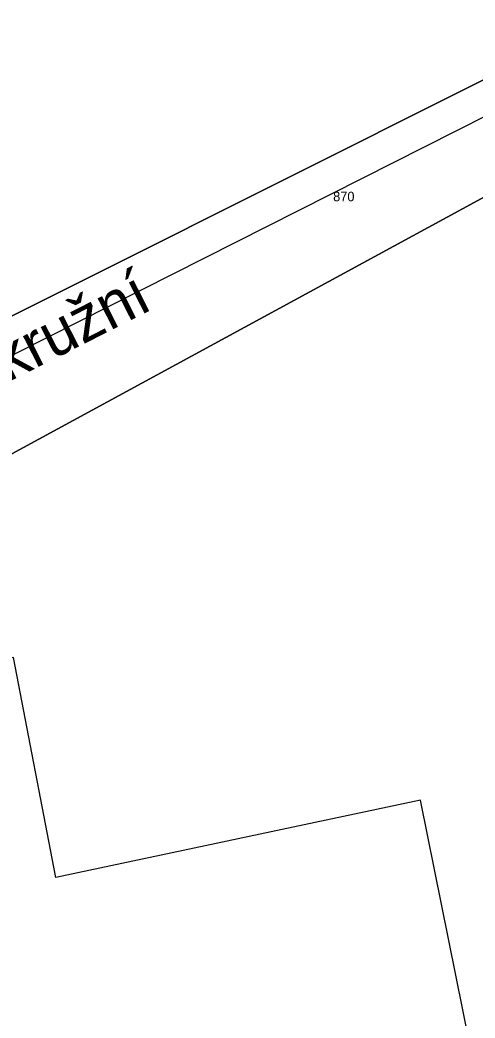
# Model space of a CAD drawing. Extents: x -873642 to -872917, y -1012962 to -1012567.
# Drawn here: x -873481.3 to -873440.9, y -1012917 to -1012828.2 of the extents above; entities that cross this region are included whole.
import ezdxf

# ---------------------------------------------------------------- set-up
doc = ezdxf.new("R2010")
doc.units = 0
for name, color, linetype in [('cisla_parcelni_kn', 7, 'Continuous'), ('osy_ulic', 7, 'Continuous'), ('parcely_kn', 7, 'Continuous'), ('ulice', 7, 'Continuous')]:
    doc.layers.add(name, color=color, linetype=linetype)

msp = doc.modelspace()

# ---------------------------------------------------------------- linework, layer by layer
at = {"layer": 'osy_ulic'}
msp.add_lwpolyline([(-873411.85, -1012822.53), (-873495.73, -1012864.97), (-873510.64, -1012868.38), (-873524.3, -1012868.21), (-873541.44, -1012862.33)], dxfattribs=at)
at = {"layer": 'parcely_kn'}
for points in [[(-873491.56, -1012871.97), (-873407.44, -1012826.19), (-873370.67, -1012811.62), (-873352.28, -1012804.24), (-873327.22, -1012794.59), (-873317.65, -1012791.79), (-873296.21, -1012784.7), (-873295.08, -1012789.07), (-873304.48, -1012791.83), (-873302.28, -1012798.85), (-873296.89, -1012797.13), (-873293, -1012795.88), (-873288.89, -1012809.97), (-873206.66, -1012788.54), (-873209.55, -1012779.29), (-873212.49, -1012767.05), (-873213.62, -1012762.14), (-873185.58, -1012756.25), (-873148.18, -1012749.22)], [(-873491.56, -1012871.97), (-873407.44, -1012826.19), (-873370.67, -1012811.62), (-873352.28, -1012804.24), (-873327.22, -1012794.59), (-873317.65, -1012791.79), (-873296.21, -1012784.7), (-873295.08, -1012789.07), (-873304.48, -1012791.83), (-873302.28, -1012798.85), (-873296.89, -1012797.13), (-873293, -1012795.88), (-873288.89, -1012809.97), (-873206.66, -1012788.54), (-873209.55, -1012779.29), (-873212.49, -1012767.05), (-873213.62, -1012762.14), (-873185.58, -1012756.25), (-873148.18, -1012749.22)], [(-873498.44, -1012787.82), (-873438.55, -1012783.17), (-873436.61, -1012786.86), (-873437.44, -1012788.27), (-873438.97, -1012789.6), (-873437.28, -1012792.66), (-873435.3, -1012792.45), (-873433.76, -1012792.56), (-873432.2, -1012793.89), (-873420.81, -1012815.05), (-873420.2, -1012816.99), (-873420.07, -1012818.95), (-873420.24, -1012820.89), (-873421.37, -1012822.77), (-873422.58, -1012824.33), (-873424.19, -1012825.53), (-873491.75, -1012859.41)], [(-873498.44, -1012787.82), (-873438.55, -1012783.17), (-873436.61, -1012786.86), (-873437.44, -1012788.27), (-873438.97, -1012789.6), (-873437.28, -1012792.66), (-873435.3, -1012792.45), (-873433.76, -1012792.56), (-873432.2, -1012793.89), (-873420.81, -1012815.05), (-873420.2, -1012816.99), (-873420.07, -1012818.95), (-873420.24, -1012820.89), (-873421.37, -1012822.77), (-873422.58, -1012824.33), (-873424.19, -1012825.53), (-873491.75, -1012859.41)], [(-873149.77, -1012848.73), (-873202.95, -1012863.9), (-873307.96, -1012890.45), (-873318.36, -1012895.27), (-873328.54, -1012899.56), (-873340.69, -1012904.93), (-873416.15, -1012938.7), (-873417.98, -1012939.52), (-873435.72, -1012947.37), (-873445.76, -1012897.62), (-873478.14, -1012904.47), (-873481.91, -1012884.93)], [(-873149.77, -1012848.73), (-873202.95, -1012863.9), (-873307.96, -1012890.45), (-873318.36, -1012895.27), (-873328.54, -1012899.56), (-873340.69, -1012904.93), (-873416.15, -1012938.7), (-873417.98, -1012939.52), (-873435.72, -1012947.37), (-873445.76, -1012897.62), (-873478.14, -1012904.47), (-873481.91, -1012884.93)], [(-873433.111, -1012961.688), (-873435.72, -1012947.37), (-873445.76, -1012897.62), (-873478.14, -1012904.47), (-873481.91, -1012884.93), (-873488.8, -1012886.1), (-873510.5, -1012890.72), (-873518.4, -1012892.32), (-873514.15, -1012917.38), (-873512.63, -1012922.93), (-873511.15, -1012929.54), (-873509.89, -1012935.71), (-873508.05, -1012945.66), (-873505.9, -1012956.95), (-873505.023, -1012961.688)], [(-873433.111, -1012961.688), (-873435.72, -1012947.37), (-873445.76, -1012897.62), (-873478.14, -1012904.47), (-873481.91, -1012884.93), (-873488.8, -1012886.1), (-873510.5, -1012890.72), (-873518.4, -1012892.32), (-873514.15, -1012917.38), (-873512.63, -1012922.93), (-873511.15, -1012929.54), (-873509.89, -1012935.71), (-873508.05, -1012945.66), (-873505.9, -1012956.95), (-873505.023, -1012961.688)]]:
    msp.add_lwpolyline(points, dxfattribs=at)
msp.add_lwpolyline([(-873407.44, -1012826.19), (-873491.56, -1012871.97), (-873510.35, -1012874.83), (-873513.75, -1012874.06), (-873521.64, -1012872.77), (-873517.87, -1012866.9), (-873506.6, -1012864.53), (-873501.14, -1012863.39), (-873495.55, -1012861.22), (-873491.75, -1012859.41), (-873424.19, -1012825.53), (-873422.58, -1012824.33), (-873421.37, -1012822.77), (-873420.24, -1012820.89), (-873420.07, -1012818.95), (-873420.2, -1012816.99), (-873420.81, -1012815.05)], close=True, dxfattribs=at)
msp.add_lwpolyline([(-873407.44, -1012826.19), (-873491.56, -1012871.97), (-873510.35, -1012874.83), (-873513.75, -1012874.06), (-873521.64, -1012872.77), (-873517.87, -1012866.9), (-873506.6, -1012864.53), (-873501.14, -1012863.39), (-873495.55, -1012861.22), (-873491.75, -1012859.41), (-873424.19, -1012825.53), (-873422.58, -1012824.33), (-873421.37, -1012822.77), (-873420.24, -1012820.89), (-873420.07, -1012818.95), (-873420.2, -1012816.99), (-873420.81, -1012815.05)], close=True, dxfattribs=at)

# ---------------------------------------------------------------- texts
at = {"layer": 'cisla_parcelni_kn'}
msp.add_text('870', height=0.85, dxfattribs=at).set_placement((-873453.508, -1012844.363))
msp.add_text('870', height=0.85, dxfattribs=at).set_placement((-873453.508, -1012844.363))
at = {"layer": 'ulice'}
msp.add_text('Okružní', height=4, rotation=26.83763, dxfattribs=at).set_placement((-873486.103, -1012862.341))

doc.saveas('drawing.dxf')
